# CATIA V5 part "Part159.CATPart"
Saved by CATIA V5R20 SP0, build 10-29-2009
Part number: FA 105700-1
Revision: ANY
Definition: UNKNOWN
Nomenclature: FA 105700-1
Source: Unknown
Bounding box of the stored display mesh (mm): x -2.853 to 2.853, y 0.2 to 2.5, z -3 to 3
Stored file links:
  C:\Users\Utente\Desktop\IO LAVORO\3D X SITO CF\CUMSA\3D files FA\FA 105712-20\Part159.CATPart
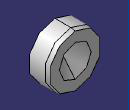
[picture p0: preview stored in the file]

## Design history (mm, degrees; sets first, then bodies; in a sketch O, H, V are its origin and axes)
Body1 "Cortar-Extruir1" (main body)
  Solid1: solid without history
